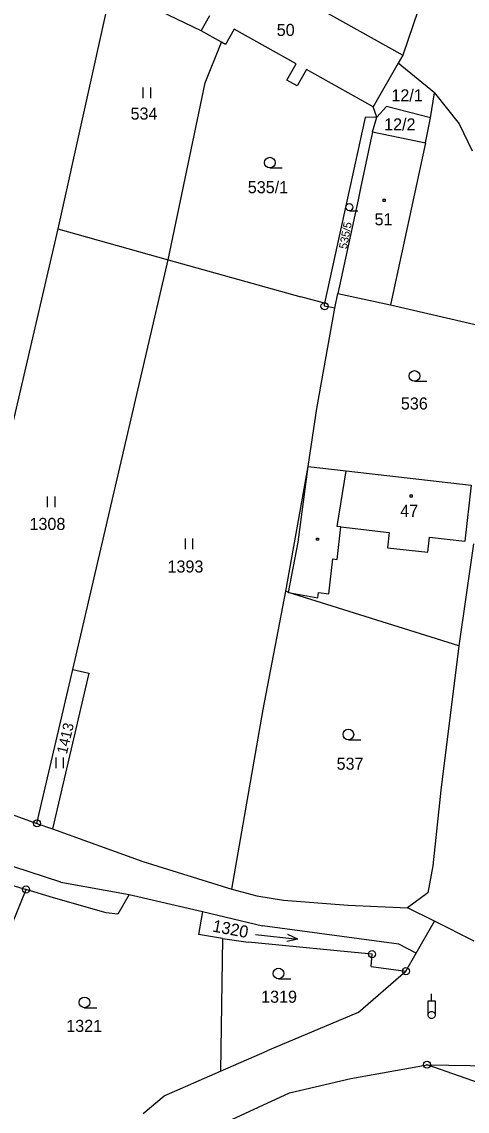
# Model space of a CAD drawing. Extents: x -796130 to -793145, y -1109506 to -1106267.
# Drawn here: x -794664.8 to -794602, y -1107830.1 to -1107676.5 of the extents above; entities that cross this region are included whole.
import ezdxf

# ---------------------------------------------------------------- set-up
doc = ezdxf.new("R2010")
doc.units = 0
for name, color, linetype in [('Vrstva 1', 7, 'Continuous'), ('Vrstva 14', 7, 'Continuous'), ('Vrstva 15', 7, 'Continuous'), ('Vrstva 2', 7, 'Continuous'), ('Vrstva 23', 7, 'Continuous'), ('Vrstva 25', 7, 'Continuous'), ('Vrstva 26', 7, 'Continuous'), ('Vrstva 28', 7, 'Continuous')]:
    doc.layers.add(name, color=color, linetype=linetype)

msp = doc.modelspace()

# ---------------------------------------------------------------- linework, layer by layer
at = {"layer": 'Vrstva 1'}
for p, q in [((-794652.3, -1107672), (-794659.77, -1107705.73)), ((-794639.55, -1107677.79), (-794646.4, -1107674.52)), ((-794608.97, -1107674.9), (-794611.1, -1107681.23)), ((-794636.69, -1107679.39), (-794639.55, -1107677.79)), ((-794634.9, -1107677.56), (-794636.11, -1107679.72)), ((-794626.17, -1107682.43), (-794634.9, -1107677.56)), ((-794638.99, -1107685.12), (-794636.69, -1107679.39)), ((-794636.11, -1107679.72), (-794636.69, -1107679.39)), ((-794611.1, -1107681.23), (-794611.76, -1107682.37)), ((-794627.46, -1107684.75), (-794626.17, -1107682.43)), ((-794624.7, -1107683.25), (-794626, -1107685.57)), ((-794615.29, -1107688.51), (-794624.7, -1107683.25)), ((-794611.76, -1107682.37), (-794615.29, -1107688.51)), ((-794606.65, -1107686.55), (-794611.76, -1107682.37)), ((-794626, -1107685.57), (-794627.46, -1107684.75)), ((-794644.19, -1107710.08), (-794638.99, -1107685.12)), ((-794607.23, -1107690.06), (-794606.65, -1107686.55)), ((-794606.65, -1107686.55), (-794603.18, -1107690.93)), ((-794614.78, -1107689.95), (-794615.29, -1107688.51)), ((-794613.42, -1107688.45), (-794614.78, -1107689.95)), ((-794607.23, -1107690.06), (-794613.42, -1107688.45)), ((-794616.43, -1107690.03), (-794622.15, -1107716.19)), ((-794614.78, -1107689.95), (-794616.43, -1107690.03)), ((-794615.4, -1107692.05), (-794614.78, -1107689.95)), ((-794607.93, -1107693.59), (-794607.23, -1107690.06)), ((-794603.18, -1107690.93), (-794601.34, -1107694.72)), ((-794615.4, -1107692.05), (-794617.1, -1107699.98)), ((-794615.4, -1107692.05), (-794607.93, -1107693.59)), ((-794617.1, -1107699.98), (-794617.44, -1107701.6)), ((-794617.44, -1107701.6), (-794620.27, -1107714.82)), ((-794659.77, -1107705.73), (-794678, -1107783.99)), ((-794659.77, -1107705.73), (-794644.19, -1107710.08)), ((-794657.65, -1107767.83), (-794644.19, -1107710.08)), ((-794644.19, -1107710.08), (-794625.5, -1107715.29)), ((-794622.15, -1107716.19), (-794625.5, -1107715.29)), ((-794620.71, -1107716.9), (-794620.27, -1107714.82)), ((-794620.27, -1107714.82), (-794612.84, -1107716.43)), ((-794623.23, -1107731.02), (-794620.71, -1107716.9)), ((-794622.16, -1107716.62), (-794622.15, -1107716.19)), ((-794620.71, -1107716.9), (-794622.16, -1107716.62)), ((-794612.84, -1107716.43), (-794599.68, -1107719.46)), ((-794624.47, -1107739.2), (-794623.23, -1107731.02)), ((-794627.6, -1107756.81), (-794624.47, -1107739.2)), ((-794624.47, -1107739.2), (-794619.11, -1107739.81)), ((-794619.11, -1107739.81), (-794601.49, -1107741.83)), ((-794601.16, -1107750.12), (-794603.21, -1107764.49)), ((-794630.81, -1107773.46), (-794627.6, -1107756.81)), ((-794627.24, -1107756.96), (-794627.6, -1107756.81)), ((-794603.21, -1107764.49), (-794627.24, -1107756.96)), ((-794603.21, -1107764.49), (-794605.77, -1107784.84)), ((-794662.7, -1107789.52), (-794657.65, -1107767.83)), ((-794657.65, -1107767.83), (-794655.39, -1107768.35)), ((-794655.39, -1107768.35), (-794660.5, -1107790.31)), ((-794635.25, -1107798.82), (-794630.81, -1107773.46)), ((-794659.34, -1107797.79), (-794706.14, -1107782.56)), ((-794678, -1107783.99), (-794662.7, -1107789.52)), ((-794605.77, -1107784.84), (-794606.91, -1107795.53)), ((-794709.81, -1107784.95), (-794664.25, -1107798.84)), ((-794662.7, -1107789.52), (-794660.5, -1107790.31)), ((-794660.5, -1107790.31), (-794647.8, -1107794.9)), ((-794647.8, -1107794.9), (-794635.25, -1107798.82)), ((-794606.91, -1107795.53), (-794607.58, -1107799.3)), ((-794659.34, -1107797.79), (-794649.7, -1107799.53)), ((-794680.15, -1107838.09), (-794664.25, -1107798.84)), ((-794660.38, -1107800.02), (-794664.25, -1107798.84)), ((-794652.97, -1107802.14), (-794660.38, -1107800.02)), ((-794649.7, -1107799.53), (-794651.32, -1107802.3)), ((-794649.7, -1107799.53), (-794639.38, -1107801.96)), ((-794635.25, -1107798.82), (-794631.69, -1107799.76)), ((-794631.69, -1107799.76), (-794627.95, -1107800.34)), ((-794607.58, -1107799.3), (-794610.46, -1107801.42)), ((-794627.95, -1107800.34), (-794618.85, -1107801.05)), ((-794618.85, -1107801.05), (-794610.46, -1107801.42)), ((-794606.66, -1107803.33), (-794610.46, -1107801.42)), ((-794651.32, -1107802.3), (-794652.97, -1107802.14)), ((-794639.38, -1107801.96), (-794639.93, -1107805.2)), ((-794639.38, -1107801.96), (-794630.92, -1107803.99)), ((-794611.67, -1107806.55), (-794630.92, -1107803.99)), ((-794609.25, -1107807.82), (-794606.66, -1107803.33)), ((-794601.08, -1107806.14), (-794606.66, -1107803.33)), ((-794636.53, -1107805.74), (-794639.93, -1107805.2)), ((-794636.53, -1107805.74), (-794636.81, -1107824.47)), ((-794636.53, -1107805.74), (-794632.93, -1107806.26)), ((-794618.92, -1107807.61), (-794632.93, -1107806.26)), ((-794615.46, -1107807.96), (-794618.92, -1107807.61)), ((-794609.25, -1107807.82), (-794611.67, -1107806.55)), ((-794610.68, -1107810.36), (-794609.25, -1107807.82)), ((-794615.58, -1107809.72), (-794615.46, -1107807.96)), ((-794617.42, -1107816.19), (-794610.68, -1107810.36)), ((-794615.58, -1107809.72), (-794610.68, -1107810.36)), ((-794617.42, -1107816.19), (-794630.24, -1107821.61)), ((-794636.81, -1107824.47), (-794630.24, -1107821.61)), ((-794644.79, -1107827.95), (-794636.81, -1107824.47)), ((-794618.46, -1107825.5), (-794607.71, -1107823.54)), ((-794607.71, -1107823.54), (-794595.06, -1107823.75)), ((-794547.69, -1107844.84), (-794607.71, -1107823.54)), ((-794627.11, -1107827.53), (-794618.46, -1107825.5)), ((-794645.15, -1107835.81), (-794627.11, -1107827.53)), ((-794647.75, -1107830.4), (-794644.79, -1107827.95))]:
    msp.add_line(p, q, dxfattribs=at)
at = {"layer": 'Vrstva 2'}
for p, q in [((-794637.76, -1107666.32), (-794611.1, -1107681.23)), ((-794639.55, -1107677.79), (-794638.35, -1107675.63)), ((-794607.93, -1107693.59), (-794612.84, -1107716.43)), ((-794625.86, -1107749.88), (-794624.47, -1107739.2)), ((-794620.36, -1107747.65), (-794619.11, -1107739.81)), ((-794601.49, -1107741.83), (-794602.38, -1107749.75)), ((-794620.39, -1107752.33), (-794619.84, -1107747.71)), ((-794619.84, -1107747.71), (-794620.36, -1107747.65)), ((-794619.84, -1107747.71), (-794613.03, -1107748.51)), ((-794613.03, -1107748.51), (-794613.28, -1107750.66)), ((-794607.59, -1107751.31), (-794607.34, -1107749.17)), ((-794607.34, -1107749.17), (-794602.38, -1107749.75)), ((-794627.24, -1107756.96), (-794625.86, -1107749.88)), ((-794613.28, -1107750.66), (-794607.59, -1107751.31)), ((-794621.56, -1107757.18), (-794621, -1107752.24)), ((-794621, -1107752.24), (-794620.39, -1107752.33)), ((-794627.24, -1107756.96), (-794623.09, -1107757.71)), ((-794623.09, -1107757.71), (-794622.99, -1107756.98)), ((-794622.99, -1107756.98), (-794621.56, -1107757.18))]:
    msp.add_line(p, q, dxfattribs=at)
at = {"layer": 'Vrstva 23'}
for p, q in [((-794647.72, -1107687.27), (-794647.72, -1107685.77)), ((-794646.72, -1107685.77), (-794646.72, -1107687.27)), ((-794629.87, -1107697.13), (-794628.12, -1107697.13)), ((-794618.66, -1107703.15), (-794617.487, -1107703.15)), ((-794609.48, -1107727.2), (-794607.73, -1107727.2)), ((-794661.2, -1107744.93), (-794661.2, -1107743.43)), ((-794660.2, -1107743.43), (-794660.2, -1107744.93)), ((-794641.77, -1107750.88), (-794641.77, -1107749.38)), ((-794640.77, -1107749.38), (-794640.77, -1107750.88)), ((-794618.8, -1107777.75), (-794617.05, -1107777.75)), ((-794660.01, -1107781.75), (-794660.01, -1107780.25)), ((-794659.01, -1107780.25), (-794659.01, -1107781.75)), ((-794631.882, -1107805.198), (-794625.917, -1107805.841)), ((-794625.917, -1107805.841), (-794627.462, -1107806.177)), ((-794625.917, -1107805.841), (-794627.355, -1107805.183)), ((-794628.65, -1107811.43), (-794626.9, -1107811.43)), ((-794656.01, -1107815.51), (-794654.26, -1107815.51))]:
    msp.add_line(p, q, dxfattribs=at)
for centre, radius in [((-794629.87, -1107696.38), 0.75), ((-794618.66, -1107702.647), 0.503), ((-794609.48, -1107726.45), 0.75), ((-794618.8, -1107777), 0.75), ((-794628.65, -1107810.68), 0.75), ((-794656.01, -1107814.76), 0.75)]:
    msp.add_circle(centre, radius, dxfattribs=at)
at = {"layer": 'Vrstva 25'}
for p, q in [((-794613.9, -1107701.54), (-794613.6, -1107701.54)), ((-794613.9, -1107701.84), (-794613.9, -1107701.54)), ((-794613.6, -1107701.84), (-794613.9, -1107701.84)), ((-794613.6, -1107701.54), (-794613.6, -1107701.84)), ((-794610.11, -1107743.23), (-794609.81, -1107743.23)), ((-794610.11, -1107743.53), (-794610.11, -1107743.23)), ((-794609.81, -1107743.23), (-794609.81, -1107743.53)), ((-794609.81, -1107743.53), (-794610.11, -1107743.53)), ((-794623.29, -1107749.3), (-794622.99, -1107749.3)), ((-794623.29, -1107749.6), (-794623.29, -1107749.3)), ((-794622.99, -1107749.3), (-794622.99, -1107749.6)), ((-794622.99, -1107749.6), (-794623.29, -1107749.6))]:
    msp.add_line(p, q, dxfattribs=at)
at = {"layer": 'Vrstva 26'}
for p, q in [((-794607.07, -1107814.54), (-794607.07, -1107813.54)), ((-794607.57, -1107816.54), (-794607.57, -1107814.54)), ((-794607.57, -1107814.54), (-794606.57, -1107814.54)), ((-794606.57, -1107814.54), (-794606.57, -1107816.54)), ((-794607.57, -1107816.44), (-794607.47, -1107816.24)), ((-794607.57, -1107816.64), (-794607.57, -1107816.44)), ((-794607.47, -1107816.84), (-794607.57, -1107816.64)), ((-794607.47, -1107816.24), (-794607.37, -1107816.14)), ((-794607.37, -1107816.94), (-794607.47, -1107816.84)), ((-794607.37, -1107816.14), (-794607.17, -1107816.04)), ((-794607.17, -1107817.04), (-794607.37, -1107816.94)), ((-794607.17, -1107816.04), (-794606.97, -1107816.04)), ((-794606.97, -1107817.04), (-794607.17, -1107817.04)), ((-794607.07, -1107816.54), (-794607.07, -1107816.54)), ((-794606.97, -1107816.04), (-794606.77, -1107816.14)), ((-794606.77, -1107816.94), (-794606.97, -1107817.04)), ((-794606.77, -1107816.14), (-794606.67, -1107816.24)), ((-794606.67, -1107816.84), (-794606.77, -1107816.94)), ((-794606.67, -1107816.24), (-794606.57, -1107816.44)), ((-794606.57, -1107816.64), (-794606.67, -1107816.84)), ((-794606.57, -1107816.44), (-794606.57, -1107816.64))]:
    msp.add_line(p, q, dxfattribs=at)
at = {"layer": 'Vrstva 28'}
for centre, radius in [((-794622.16, -1107716.62), 0.5), ((-794622.16, -1107716.62), 0.01), ((-794662.7, -1107789.52), 0.5), ((-794662.7, -1107789.52), 0.01), ((-794664.25, -1107798.84), 0.5), ((-794664.25, -1107798.84), 0.01), ((-794615.46, -1107807.96), 0.5), ((-794615.46, -1107807.96), 0.01), ((-794610.68, -1107810.36), 0.5), ((-794610.68, -1107810.36), 0.01), ((-794607.71, -1107823.54), 0.5), ((-794607.71, -1107823.54), 0.01)]:
    msp.add_circle(centre, radius, dxfattribs=at)

# ---------------------------------------------------------------- texts
at = {"layer": 'Vrstva 14'}
for s, p in [('12/1', (-794612.736, -1107687.74)), ('534', (-794649.51, -1107690.31)), ('12/2', (-794613.763, -1107691.84)), ('535/1', (-794632.98, -1107700.69)), ('536', (-794611.4, -1107731.18)), ('1308', (-794663.759, -1107748.16)), ('1393', (-794644.3, -1107754.16)), ('537', (-794620.46, -1107781.96)), ('1319', (-794631.103, -1107814.81)), ('1321', (-794658.573, -1107818.92))]:
    msp.add_text(s, height=1.7, dxfattribs=at).set_placement(p)
for s, height, rotation, p in [('535/5', 1.14, 79.2, (-794619.019, -1107708.617)), ('1413', 1.48, 76.63653, (-794658.498, -1107779.84)), ('1320', 1.7, 349.2, (-794638.05, -1107804.755))]:
    msp.add_text(s, height=height, rotation=rotation, dxfattribs=at).set_placement(p)
at = {"layer": 'Vrstva 15'}
for s, p in [('50', (-794628.9, -1107678.52)), ('51', (-794615.11, -1107705.21)), ('47', (-794611.49, -1107746.31))]:
    msp.add_text(s, height=1.7, dxfattribs=at).set_placement(p)

doc.saveas('drawing.dxf')
